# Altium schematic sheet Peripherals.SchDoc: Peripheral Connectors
size A4; Organization: Team Ashwathama; Address1: Colorado Boulder; Address2: Author- Deepesh Sonigra; Address3: Self Checkout Shopping Cart; DocumentNumber: 1; Revision: 1.0; SheetNumber: 7; SheetTotal: 7
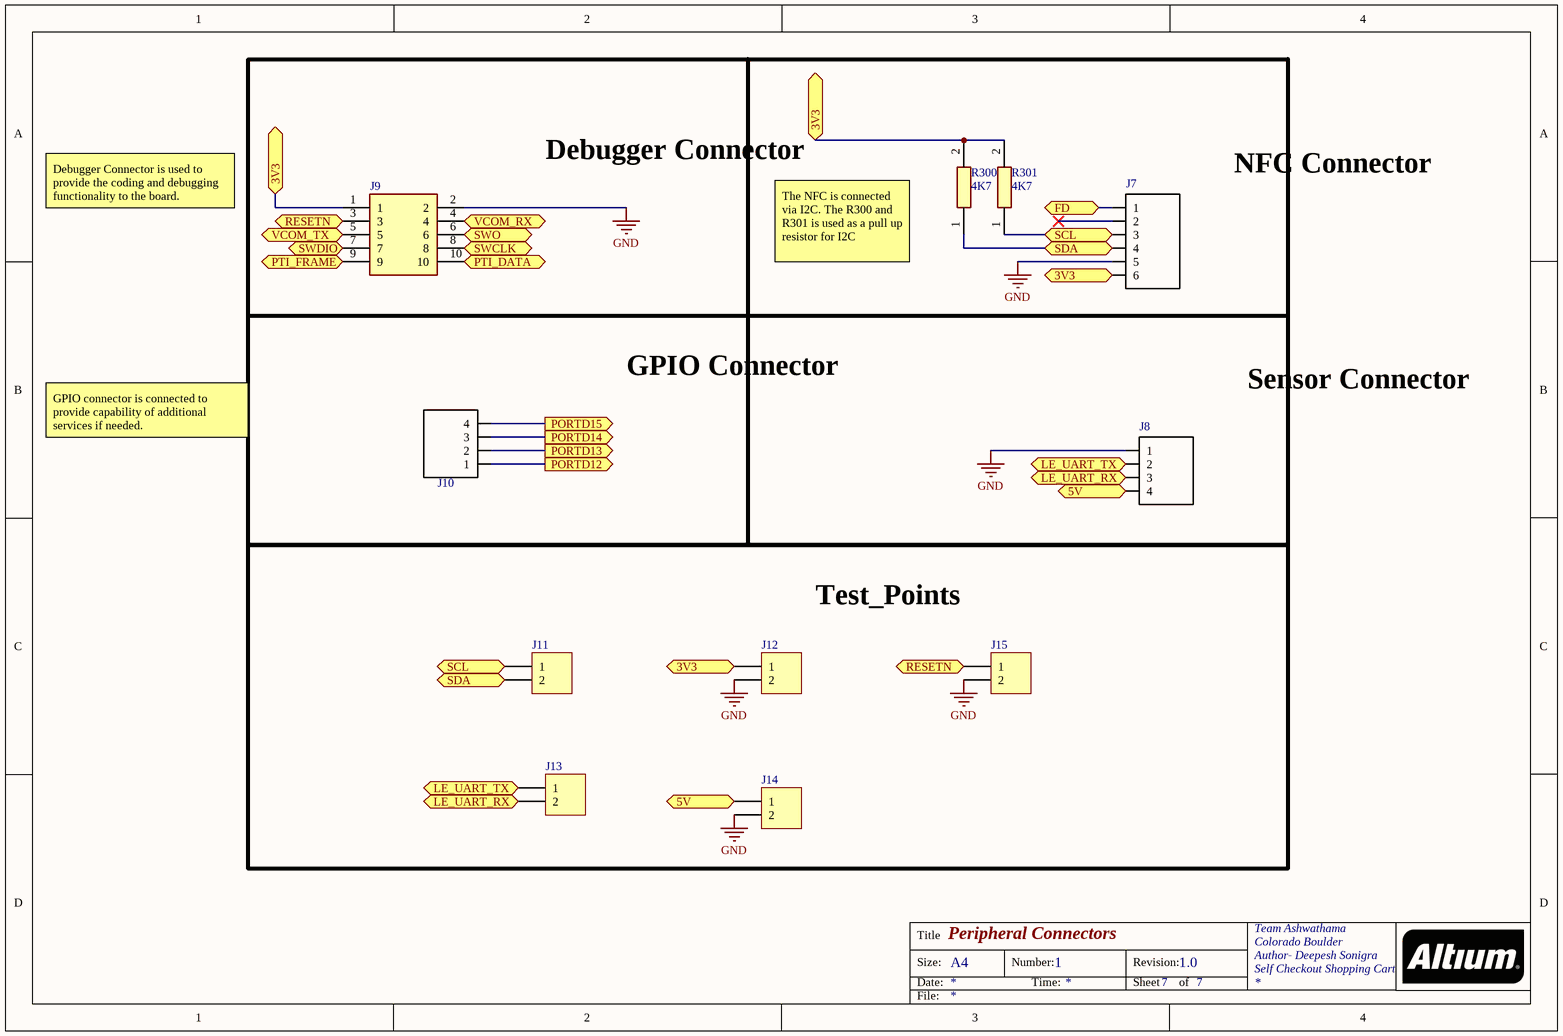
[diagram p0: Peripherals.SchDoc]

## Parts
J7  BG300-06-X-X-A_REVC  [*GCT_BG300-06-X-X-A_REVC]  (value not drawn)
J8  BG301-04-X-XXXX-X-X_REVC  [*GCT_BG301-04-X-XXXX-X-X_REVC]  (value not drawn)
J9  FTSH-105-01-L-DV-K-TR  [FTSH10501LDVKTR]  (value not drawn)
J10  BG301-04-X-XXXX-X-X_REVC  [*GCT_BG301-04-X-XXXX-X-X_REVC]  (value not drawn)
J11  Header 2  [HDR1X2]  (value not drawn)
J12  Header 2  [HDR1X2]  (value not drawn)
J13  Header 2  [HDR1X2]  (value not drawn)
J14  Header 2  [HDR1X2]  (value not drawn)
J15  Header 2  [HDR1X2]  (value not drawn)
R300  value 4K7  [RESC1608X50N]  (hidden comment: RCS06034K70FKEA)
R301  value 4K7  [RESC1608X50N]  (hidden comment: RCS06034K70FKEA)

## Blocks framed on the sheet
Test_Points: J11-J15

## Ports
3V3, 5V, FD, LE_UART_RX, LE_UART_TX, PORTD12, PORTD13, PORTD14, PORTD15, PTI_DATA, PTI_FRAME, RESETN, SCL, SDA, SWCLK, SWDIO, SWO, VCOM_RX, VCOM_TX

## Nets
GND: J7.5 J8.1 J9.2 J12.2 J14.2 J15.2
3V3: J7.6 J9.1 J12.1 R300.2 R301.2 ; port 3V3
5V: J8.4 J14.1 ; port 5V
FD: J7.1 ; port FD
LE_UART_RX: J8.3 J13.2 ; port LE_UART_RX
LE_UART_TX: J8.2 J13.1 ; port LE_UART_TX
PORTD12: J10.1 ; port PORTD12
PORTD13: J10.2 ; port PORTD13
PORTD14: J10.3 ; port PORTD14
PORTD15: J10.4 ; port PORTD15
PTI_DATA: J9.10 ; port PTI_DATA
PTI_FRAME: J9.9 ; port PTI_FRAME
RESETN: J9.3 J15.1 ; port RESETN
SCL: J7.3 J11.1 R301.1 ; port SCL
SDA: J7.4 J11.2 R300.1 ; port SDA
SWCLK: J9.8 ; port SWCLK
SWDIO: J9.7 ; port SWDIO
SWO: J9.6 ; port SWO
VCOM_RX: J9.4 ; port VCOM_RX
VCOM_TX: J9.5 ; port VCOM_TX

Not connected (* = marked no-connect by the designer): J7 2*

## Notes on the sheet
- (near J9) Debugger Connector
- NFC Connector
- Debugger Connector is used to provide the coding and debugging functionality to the board.
- The NFC is connected via I2C. The R300 and R301 is used as a pull up resistor for I2C
- (near J10) GPIO Connector
- GPIO connector is connected to provide capability of additional services if needed.
- Sensor Connector

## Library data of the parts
J7 = BG300-06-X-X-A_REVC: 6 POS Right Angle Header; Manufacturer_Part_Number: BG300-06-A-L-A; Manufacturer_Name: Global Connector Technology; Detailed Description: 6 Position Receptacle Connector Surface Mount, Right Angle
J8 J10 = BG301-04-X-XXXX-X-X_REVC: 4 POS Right Angle Header; Manufacturer_Part_Number: BG301-04-A-0540-L-B; Manufacturer_Name: Global Connector Technology
J9 = FTSH-105-01-L-DV-K-TR: Connector; Manufacturer_Name: SAMTEC
J11-J15 = Header 2: Header, 2-Pin; Manufacturer_Part_Number: BG301-04-A-0540-L-B; Manufacturer_Name: Global Connector Technology
R300 R301 = RCS06034K70FKEA: Resistor; Manufacturer_Name: Vishay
